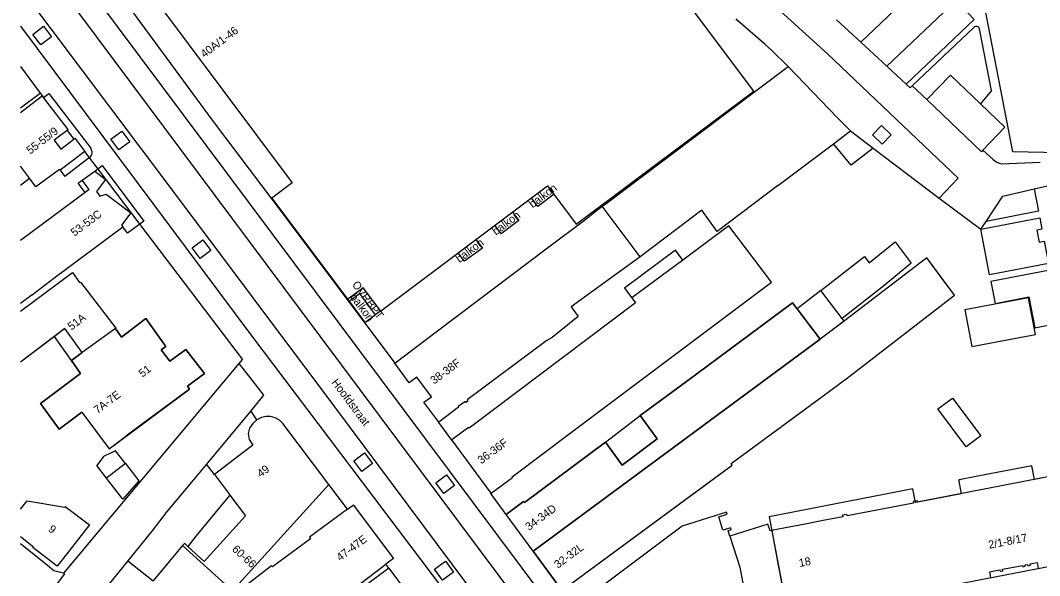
# Model space of a CAD drawing. Extents: x 194485 to 197793, y 468269 to 470822.
# Drawn here: x 194485.4 to 194638.3, y 469431.3 to 469514.5 of the extents above; entities that cross this region are included whole.
import ezdxf

# ---------------------------------------------------------------- set-up
doc = ezdxf.new("R2010")
doc.units = 0
for name, color, linetype in [('BAG plantopografie panden grensvlak pand', 7, 'Continuous'), ('BAG plantopografie panden lijnelement overig', 7, 'Continuous'), ('BAG plantopografie panden tekst opmerking', 7, 'Continuous'), ('BGT begrenzing pand op maaiveld onder overbouw', 7, 'Continuous'), ('BGT grensvlak gebouwinstallatie plus 1', 7, 'Continuous'), ('BGT grensvlak overig bouwwerk', 7, 'Continuous'), ('BGT grensvlak pand deel overbouw', 7, 'Continuous'), ('BGT grensvlak pand min 1', 7, 'Continuous'), ('BGT grensvlak pand op maaiveld', 7, 'Continuous'), ('BGT grensvlak pand op maaiveld LR', 7, 'Continuous'), ('BGT grensvlak wegdeel', 7, 'Continuous'), ('BGT tekst huisnummerreeks', 7, 'Continuous'), ('BGT tekst huisnummerreeks min 1', 7, 'Continuous'), ('BGT tekst openbare ruimte label weg', 7, 'Continuous'), ('GEM grensvlak beperking object', 7, 'Continuous')]:
    doc.layers.add(name, color=color, linetype=linetype)

msp = doc.modelspace()

# ---------------------------------------------------------------- linework, layer by layer
at = {"layer": 'BAG plantopografie panden grensvlak pand'}
for p, q in [((194595.38, 469503.93), (194561.96, 469548.58)), ((194498.06, 469527.77), (194526.18, 469490.2)), ((194568.78, 469484.02), (194595.38, 469503.93)), ((194526.18, 469490.2), (194523.12, 469487.91)), ((194539.4, 469470.98), (194564.48, 469489.76)), ((194564.48, 469489.76), (194568.78, 469484.02)), ((194523.12, 469487.91), (194534.48, 469472.74)), ((194534.7, 469472.44), (194536.26, 469473.6)), ((194536.26, 469473.6), (194538.64, 469470.42)), ((194534.48, 469472.74), (194534.7, 469472.44)), ((194539.4, 469470.98), (194538.64, 469470.42))]:
    msp.add_line(p, q, dxfattribs=at)
at = {"layer": 'BAG plantopografie panden lijnelement overig'}
for p, q in [((194563, 469486.65), (194562.04, 469487.93)), ((194565.44, 469488.48), (194563, 469486.65)), ((194559.21, 469485.82), (194560.17, 469484.53)), ((194560.17, 469484.53), (194557.51, 469482.54)), ((194557.51, 469482.54), (194556.55, 469483.83)), ((194553.73, 469481.71), (194554.69, 469480.43)), ((194552.03, 469478.44), (194551.07, 469479.72)), ((194554.69, 469480.43), (194552.03, 469478.44)), ((194534.48, 469472.74), (194536.79, 469474.47)), ((194536.79, 469474.47), (194539.4, 469470.98)), ((194534.7, 469472.44), (194537.09, 469469.26)), ((194537.09, 469469.26), (194538.64, 469470.42))]:
    msp.add_line(p, q, dxfattribs=at)
at = {"layer": 'BGT begrenzing pand op maaiveld onder overbouw'}
for p, q in [((194492.41, 469498.06), (194490.47, 469496.57)), ((194490.47, 469496.57), (194491.47, 469495.26)), ((194491.47, 469495.26), (194493.41, 469496.75))]:
    msp.add_line(p, q, dxfattribs=at)
for points in [[(194591.81, 469437.24), (194593.3, 469432.6), (194594.45, 469426.43), (194594.35, 469426.4), (194594.73, 469424.46), (194593.08, 469423.93)], [(194598.08, 469438.08), (194599.06, 469432.91), (194600.38, 469426.02)]]:
    msp.add_lwpolyline(points, dxfattribs=at)
at = {"layer": 'BGT grensvlak gebouwinstallatie plus 1'}
for p, q in [((194488.9, 469502.98), (194489.69, 469503.59)), ((194489.69, 469503.59), (194495.98, 469495.37)), ((194609.88, 469497.97), (194613.3, 469495.4)), ((194610.01, 469492.85), (194607.33, 469496.06)), ((194613.3, 469495.4), (194610.01, 469492.85)), ((194495.79, 469493.97), (194492.1, 469491.15)), ((194491.36, 469492.11), (194492.1, 469491.15)), ((194496.56, 469491.97), (194497.69, 469492.81)), ((194497.69, 469492.81), (194503.9, 469484.44)), ((194485.41, 469489.87), (194486.76, 469490.9)), ((194494.09, 469490.13), (194494.7, 469490.59)), ((194495.11, 469488.76), (194494.09, 469490.13)), ((194503.9, 469484.44), (194501.49, 469482.65)), ((194501.49, 469482.65), (194500.79, 469483.59)), ((194605.45, 469474.05), (194601.88, 469471.33)), ((194608.96, 469469.44), (194608.66, 469469.84)), ((194493.1, 469463.57), (194490.52, 469467.17)), ((194573.14, 469451.31), (194578.36, 469455.31))]:
    msp.add_line(p, q, dxfattribs=at)
for points in [[(194584.78, 469478.63), (194583.68, 469480.11), (194576.03, 469474.43), (194577.13, 469472.95)], [(194501.16, 469448.13), (194503.18, 469445.53), (194500.8, 469442.8), (194498.35, 469445.95)], [(194516.83, 469443.4), (194515.54, 469441.85), (194511.71, 469437.26), (194510.5, 469435.7)]]:
    msp.add_lwpolyline(points, dxfattribs=at)
msp.add_arc((194495.18, 469494.76), 1, 307.3973, 37.4081, dxfattribs=at)
at = {"layer": 'BGT grensvlak overig bouwwerk'}
msp.add_lwpolyline([(194613.2, 469497.39), (194614.53, 469498.77), (194615.98, 469497.37), (194614.65, 469496), (194613.2, 469497.39)], dxfattribs=at)
at = {"layer": 'BGT grensvlak pand deel overbouw'}
msp.add_line((194492.41, 469498.06), (194493.41, 469496.75), dxfattribs=at)
msp.add_lwpolyline([(194598.08, 469438.08), (194597.84, 469438.04), (194597.52, 469439.04), (194594.67, 469438.14), (194591.81, 469437.24)], dxfattribs=at)
at = {"layer": 'BGT grensvlak pand min 1'}
msp.add_lwpolyline([(194600.54, 469425.14), (194657.87, 469436.23), (194657.64, 469437.39), (194662.3, 469444.43), (194663.53, 469444.64), (194664.1, 469445.45), (194663.92, 469446.41), (194663.11, 469446.92), (194662.42, 469450.59), (194619.66, 469442.27), (194619.26, 469444.32), (194597.68, 469440.12), (194600.54, 469425.14)], dxfattribs=at)
at = {"layer": 'BGT grensvlak pand op maaiveld'}
for p, q in [((194485.41, 469507.61), (194488.38, 469503.66)), ((194573.45, 469487.26), (194600.53, 469507.63)), ((194485.41, 469501.43), (194488.38, 469503.66)), ((194488.71, 469503.22), (194485.41, 469500.69)), ((194488.9, 469502.98), (194488.71, 469503.22)), ((194607.33, 469496.06), (194609.88, 469497.97)), ((194598.95, 469489.76), (194607.33, 469496.06)), ((194495.08, 469494.9), (194491.36, 469492.11)), ((194486.76, 469490.9), (194485.41, 469492.71)), ((194494.7, 469490.59), (194496.56, 469491.97)), ((194496.56, 469491.97), (194498.14, 469490.77)), ((194495.72, 469489.21), (194494.7, 469490.59)), ((194498.2, 469490.7), (194496.83, 469488.89)), ((194498.14, 469490.77), (194498.21, 469490.72)), ((194498.21, 469490.72), (194498.2, 469490.7)), ((194495.72, 469489.21), (194495.11, 469488.76)), ((194496.83, 469488.89), (194497.35, 469488.18)), ((194495.11, 469488.76), (194485.41, 469481.56)), ((194497.35, 469488.18), (194498.27, 469488.52)), ((194498.27, 469488.52), (194501.99, 469485.7)), ((194571.57, 469485.83), (194572.68, 469486.68)), ((194572.68, 469486.68), (194573.45, 469487.26)), ((194587.6, 469486.1), (194578.36, 469479.13)), ((194629.44, 469483.23), (194629.44, 469483.24)), ((194616.6, 469481.33), (194619.01, 469478.16)), ((194547.96, 469468.02), (194564.46, 469480.45)), ((194578.36, 469479.13), (194568, 469471.59)), ((194584.78, 469478.63), (194577.13, 469472.95)), ((194624.16, 469475.16), (194621.33, 469478.96)), ((194608.66, 469469.84), (194605.45, 469474.05)), ((194487.16, 469473.43), (194485.41, 469472.09)), ((194605.35, 469466.78), (194601.88, 469471.33)), ((194608.96, 469469.44), (194605.35, 469466.78)), ((194499.72, 469468.4), (194499.66, 469468.36)), ((194541.55, 469463.19), (194547.96, 469468.02)), ((194490.52, 469467.17), (194485.41, 469463.34)), ((194493.1, 469463.57), (194494.68, 469464.79)), ((194555.99, 469443.67), (194550.12, 469451.67)), ((194501.16, 469448.13), (194499.7, 469450.03)), ((194498.35, 469445.95), (194496.88, 469447.85)), ((194501.16, 469448.13), (194498.35, 469445.95))]:
    msp.add_line(p, q, dxfattribs=at)
for points in [[(194641.2, 469494.68), (194634.23, 469494.84), (194629.28, 469520.44)], [(194600.53, 469507.63), (194607.92, 469500), (194609.88, 469497.97)], [(194492.41, 469498.06), (194492.57, 469498.18), (194488.9, 469502.98)], [(194493.41, 469496.75), (194493.57, 469496.87), (194495.08, 469494.9)], [(194491.36, 469492.11), (194491.28, 469492.21), (194487.73, 469489.6), (194486.76, 469490.9)], [(194598.95, 469489.76), (194589.92, 469482.92), (194587.6, 469486.1)], [(194637.43, 469489.32), (194638.09, 469485.93), (194630.23, 469484.41)], [(194630.23, 469484.41), (194632.76, 469488.18), (194637.43, 469489.32)], [(194564.46, 469480.45), (194570.19, 469484.77), (194571.57, 469485.83)], [(194501.99, 469485.7), (194500.59, 469483.85), (194500.79, 469483.59)], [(194629.44, 469483.24), (194638.28, 469484.96), (194638.61, 469483.24), (194637.85, 469483.1), (194638.21, 469481.29), (194638.96, 469481.43), (194639.61, 469478.11), (194630.76, 469476.4), (194629.44, 469483.23)], [(194487.16, 469473.43), (194490.45, 469475.9), (194500.79, 469483.59)], [(194555.99, 469443.67), (194559.22, 469446.04), (194559.16, 469446.14), (194568.64, 469453.28), (194585.45, 469465.86), (194598.04, 469475.33), (194591.66, 469483.74), (194584.78, 469478.63)], [(194605.45, 469474.05), (194611.99, 469479.14), (194612.69, 469478.23), (194616.6, 469481.33)], [(194619.01, 469478.16), (194614.9, 469474.76), (194608.66, 469469.84)], [(194621.33, 469478.96), (194609.02, 469469.49), (194608.96, 469469.44)], [(194485.41, 469470.97), (194493.25, 469476.75), (194494.3, 469475.26), (194494.41, 469475.31), (194499.72, 469468.4)], [(194630.95, 469475.41), (194631.59, 469472.12), (194636.64, 469473.11), (194637.56, 469468.44), (194641.33, 469469.19), (194639.8, 469477.13), (194630.95, 469475.41)], [(194566.73, 469429.01), (194567.24, 469429.38), (194567.15, 469429.52), (194586.9, 469444.03), (194592.14, 469447.88), (194592.02, 469448.12), (194605.61, 469458.1), (194609.65, 469461.12), (194625.5, 469473.36), (194624.16, 469475.16)], [(194577.13, 469472.95), (194577.68, 469472.2), (194552.71, 469453.41), (194552.61, 469453.53), (194550.12, 469451.67)], [(194601.88, 469471.33), (194601.2, 469472.22), (194585.33, 469460.44), (194578.36, 469455.31)], [(194627.05, 469471.18), (194628.09, 469465.66), (194634.44, 469466.85), (194637.62, 469467.45), (194636.58, 469472.98), (194627.05, 469471.18)], [(194568, 469471.59), (194569.06, 469470.14), (194565.14, 469467), (194564.38, 469466.55), (194552.39, 469457.65), (194552.49, 469457.47), (194552.27, 469457.29), (194552.16, 469457.42), (194551.05, 469456.67), (194551.12, 469456.55), (194548.16, 469454.32)], [(194499.66, 469468.36), (194500.56, 469467.05), (194504.21, 469469.84), (194507.23, 469465.68), (194506.52, 469465.18), (194507.8, 469463.49), (194510.24, 469465.24), (194513.03, 469461.6), (194510.46, 469459.71), (194510.79, 469459.27), (194501.44, 469452.36)], [(194494.68, 469464.79), (194492.09, 469468.34), (194490.52, 469467.17)], [(194494.61, 469455.83), (194491.24, 469453.3), (194488.44, 469457.12), (194494.45, 469461.61), (194493.1, 469463.57)], [(194548.16, 469454.32), (194545.93, 469457.31), (194547.07, 469458.13), (194544.88, 469461.09), (194543.72, 469460.2), (194541.55, 469463.19)], [(194623.02, 469456.33), (194625.2, 469457.94), (194629.44, 469452.26), (194627.23, 469450.64), (194623.02, 469456.33)], [(194494.61, 469455.83), (194498.71, 469450.34), (194501.44, 469452.36)], [(194531.68, 469444.96), (194524.79, 469454.13), (194524.26, 469454.61), (194523.63, 469454.98), (194522.94, 469455.18), (194522.25, 469455.19), (194521.56, 469455.03), (194520.89, 469454.7)], [(194578.36, 469455.31), (194580.9, 469451.82), (194575.64, 469447.9), (194573.14, 469451.31)], [(194520.89, 469454.7), (194520.25, 469454.14), (194519.78, 469453.42), (194519.59, 469452.62), (194519.72, 469451.71), (194520.29, 469450.86), (194518.84, 469449.77), (194514.51, 469446.49)], [(194573.14, 469451.31), (194560.99, 469442.3), (194560.88, 469442.44), (194558.26, 469440.5)], [(194499.7, 469450.03), (194497.86, 469449.18), (194496.88, 469447.85)], [(194644.03, 469447.01), (194637.5, 469445.75), (194637.11, 469447.79), (194630.54, 469446.51), (194626.43, 469445.71), (194626.3, 469445.69), (194626.18, 469445.66), (194626.12, 469445.65), (194626.15, 469445.46), (194626.52, 469443.6), (194619.99, 469442.33), (194619.94, 469442.56), (194619.69, 469442.51), (194619.37, 469442.45), (194619.29, 469442.43), (194619.33, 469442.2), (194609.39, 469440.27), (194609.34, 469440.5), (194608.69, 469440.37), (194608.73, 469440.15), (194605.82, 469439.58), (194603.09, 469439.05), (194598.3, 469438.12), (194598.2, 469438.1), (194598.08, 469438.08)], [(194514.51, 469446.49), (194516.79, 469443.46), (194516.83, 469443.4)], [(194509.71, 469435.86), (194517.2, 469429.05), (194531.68, 469444.96)], [(194516.83, 469443.4), (194519.18, 469440.28), (194512.95, 469433.46), (194510.5, 469435.7)], [(194485.41, 469441.27), (194486.42, 469442.55), (194492.09, 469441.59), (194492.12, 469441.69), (194495.77, 469438.93), (194490.93, 469432.75)], [(194534.46, 469441.27), (194535.3, 469441.9), (194535.34, 469441.92), (194541.35, 469433.89), (194540.24, 469433.05)], [(194534.46, 469441.27), (194528.79, 469437.08), (194528.92, 469436.84), (194523.21, 469432.64), (194523.07, 469432.81), (194506.8, 469420.26)], [(194562.31, 469434.97), (194558.25, 469440.49), (194558.26, 469440.5)], [(194591.81, 469437.24), (194591.55, 469438.06), (194592.02, 469438.22), (194591.94, 469438.5), (194590.77, 469438.13), (194590.14, 469440.14), (194591.41, 469440.54), (194591.31, 469440.84), (194584.68, 469438.73), (194572.88, 469429.9), (194570.53, 469428.14)], [(194490.93, 469432.75), (194487.29, 469435.52), (194487.38, 469435.6), (194485.41, 469437.15)], [(194510.5, 469435.7), (194510.1, 469436.08), (194510.01, 469436.16), (194509.71, 469435.86)], [(194566.73, 469429.01), (194566.73, 469429.01), (194562.31, 469434.97)], [(194512.54, 469412.81), (194512.72, 469412.58), (194528.69, 469424.55), (194528.62, 469424.76), (194534.77, 469429.2), (194534.92, 469429), (194540.24, 469433.05)], [(194540.69, 469432.46), (194528.13, 469423.12), (194530.88, 469419.32), (194531.5, 469419.73), (194540.88, 469406.92), (194540.29, 469406.55), (194543.77, 469401.87), (194545.64, 469403.29)], [(194540.69, 469432.46), (194553.07, 469415.78), (194553.11, 469415.72)], [(194630.51, 469430.93), (194630.97, 469431.02), (194630.8, 469431.91), (194631.51, 469432.04), (194632.32, 469432.2), (194632.36, 469431.99), (194632.75, 469432.06), (194632.71, 469432.28), (194635.69, 469432.86), (194635.73, 469432.64), (194636.11, 469432.72), (194636.07, 469432.93), (194636.46, 469433.01), (194636.51, 469432.79), (194636.89, 469432.87), (194636.85, 469433.09), (194637.33, 469433.18), (194637.88, 469433.29), (194638.05, 469432.39), (194638.55, 469432.49)]]:
    msp.add_lwpolyline(points, dxfattribs=at)
at = {"layer": 'BGT grensvlak pand op maaiveld LR'}
for p, q in [((194578.36, 469479.13), (194572.68, 469486.68)), ((194499.66, 469468.36), (194494.68, 469464.79)), ((194562.31, 469434.97), (194605.35, 469466.78))]:
    msp.add_line(p, q, dxfattribs=at)
at = {"layer": 'BGT grensvlak wegdeel'}
for p, q in [((194489.33, 469527.8), (194546.18, 469451.79)), ((194625.74, 469517.54), (194615.34, 469507.67)), ((194593.02, 469514.49), (194592.73, 469514.76)), ((194597.03, 469510.96), (194593.02, 469514.49)), ((194628.4, 469513.5), (194619.17, 469504.73)), ((194631.05, 469504.02), (194629.26, 469513.28)), ((194615.34, 469507.67), (194611.43, 469511.3)), ((194618.24, 469504.98), (194615.34, 469507.67)), ((194618.84, 469504.42), (194618.24, 469504.98)), ((194619.17, 469504.73), (194618.84, 469504.42)), ((194619.17, 469504.73), (194621.37, 469502.69)), ((194488.38, 469503.66), (194488.71, 469503.22)), ((194629.55, 469494.86), (194621.37, 469502.69)), ((194631.05, 469504.02), (194629.38, 469502.05)), ((194613.3, 469495.4), (194623.21, 469487.92)), ((194629.77, 469495.09), (194629.55, 469494.86)), ((194629.77, 469495.09), (194631.24, 469493.73)), ((194503.38, 469483.96), (194495.08, 469494.9)), ((194632.52, 469493.03), (194638.34, 469493.31)), ((194637.43, 469489.32), (194640.36, 469489.95)), ((194623.21, 469487.92), (194629.44, 469483.23)), ((194629.44, 469483.24), (194630.23, 469484.41)), ((194518.74, 469463.79), (194503.38, 469483.96)), ((194518.19, 469463.14), (194491.89, 469431.69)), ((194518.74, 469463.79), (194518.19, 469463.14)), ((194519.96, 469456.04), (194513.34, 469448.05)), ((194520.89, 469454.7), (194519.96, 469456.04)), ((194546.18, 469451.79), (194566.24, 469424.96)), ((194514.51, 469446.49), (194513.34, 469448.05)), ((194534.46, 469441.27), (194531.68, 469444.96)), ((194489.46, 469432.83), (194485.41, 469436.1)), ((194509.71, 469435.86), (194505.3, 469430.53)), ((194501.54, 469433.56), (194497.89, 469429.03)), ((194501.54, 469433.56), (194505.3, 469430.53)), ((194540.69, 469432.46), (194540.24, 469433.05)), ((194492.05, 469431.57), (194488.91, 469427.55)), ((194492.05, 469431.57), (194491.89, 469431.69))]:
    msp.add_line(p, q, dxfattribs=at)
for points in [[(194491.72, 469529.6), (194495.66, 469524.77), (194514.32, 469499.38), (194525.12, 469485.09), (194541.55, 469463.19)], [(194611.43, 469511.3), (194623.56, 469522.81), (194626.7, 469525.17), (194624.2, 469528.3)], [(194486.62, 469525.78), (194527.36, 469471.14), (194560.25, 469427.17)], [(194623.21, 469487.92), (194626.04, 469490.88), (194606.45, 469509.54), (194591.27, 469523.36)], [(194485.41, 469519.38), (194508.02, 469489.28), (194532.51, 469456.6), (194552.3, 469430.08)], [(194618.24, 469504.98), (194628.45, 469514.68), (194625.74, 469517.54)], [(194485.41, 469513.67), (194520.14, 469467.24), (194536.67, 469445.35), (194554.25, 469422.05)], [(194488.87, 469513.67), (194490.08, 469512.08), (194488.5, 469510.86), (194487.28, 469512.45), (194488.87, 469513.67)], [(194611.43, 469511.3), (194609.59, 469513), (194607.79, 469514.64)], [(194597.03, 469510.96), (194598.1, 469510.01), (194600.53, 469507.63)], [(194621.37, 469502.69), (194624.88, 469506.35), (194629.38, 469502.05)], [(194629.38, 469502.05), (194633.06, 469498.53), (194629.77, 469495.09)], [(194500.61, 469497.96), (194501.8, 469496.33), (194500.18, 469495.14), (194498.99, 469496.76), (194500.61, 469497.96)], [(194512.77, 469481.67), (194513.97, 469480.08), (194512.38, 469478.88), (194511.19, 469480.47), (194512.77, 469481.67)], [(194518.19, 469463.14), (194520.17, 469460.56), (194521.88, 469458.36), (194519.96, 469456.04)], [(194550.12, 469451.67), (194550.1, 469451.65), (194548.14, 469454.3), (194548.16, 469454.32)], [(194537.02, 469449.73), (194538.21, 469448.12), (194536.61, 469446.92), (194535.4, 469448.53), (194537.02, 469449.73)], [(194513.34, 469448.05), (194511.31, 469445.61), (194507.44, 469440.97), (194505.12, 469437.99), (194501.54, 469433.56)], [(194548.92, 469443.61), (194547.72, 469445.22), (194549.33, 469446.42), (194550.52, 469444.81), (194548.92, 469443.61)], [(194558.26, 469440.5), (194555.96, 469443.64), (194555.99, 469443.67)], [(194491.89, 469431.69), (194490.41, 469432.05), (194489.46, 469432.83)], [(194549.14, 469433.47), (194550.34, 469431.86), (194548.73, 469430.66), (194547.53, 469432.27), (194549.14, 469433.47)]]:
    msp.add_lwpolyline(points, dxfattribs=at)
for centre, radius, start, end in [((194628.77, 469513.14), 0.513, 15.3449, 135.7708), ((194633.79, 469496.85), 4.03, 230.8123, 251.7037)]:
    msp.add_arc(centre, radius, start, end, dxfattribs=at)
at = {"layer": 'GEM grensvlak beperking object'}
for p, q in [((194499.66, 469468.36), (194494.68, 469464.79)), ((194605.35, 469466.78), (194562.31, 469434.97))]:
    msp.add_line(p, q, dxfattribs=at)
for points in [[(194562.31, 469434.97), (194566.73, 469429.01), (194567.24, 469429.38), (194567.15, 469429.52), (194592.14, 469447.88), (194592.02, 469448.12), (194605.61, 469458.1), (194609.65, 469461.12), (194625.5, 469473.36), (194621.33, 469478.96), (194609.02, 469469.49), (194605.35, 469466.78)], [(194485.41, 469470.97), (194493.25, 469476.75), (194494.3, 469475.26), (194494.41, 469475.31), (194499.72, 469468.4), (194499.66, 469468.36)], [(194562.31, 469434.97), (194558.25, 469440.49), (194560.88, 469442.44), (194560.99, 469442.3), (194573.14, 469451.31), (194575.64, 469447.9), (194580.9, 469451.82), (194578.36, 469455.31), (194585.33, 469460.44), (194601.2, 469472.22), (194605.35, 469466.78)], [(194494.68, 469464.79), (194493.1, 469463.57), (194494.45, 469461.61), (194488.44, 469457.12), (194491.24, 469453.3), (194494.61, 469455.83), (194498.71, 469450.34), (194510.79, 469459.27), (194510.46, 469459.71), (194513.03, 469461.6), (194510.24, 469465.24), (194507.8, 469463.49), (194506.52, 469465.18), (194507.23, 469465.68), (194504.21, 469469.84), (194500.56, 469467.05), (194499.66, 469468.36)], [(194494.68, 469464.79), (194492.09, 469468.34), (194485.41, 469463.34)], [(194485.41, 469441.27), (194486.42, 469442.55), (194492.09, 469441.59), (194492.12, 469441.69), (194495.77, 469438.93), (194490.93, 469432.75), (194487.29, 469435.52), (194487.38, 469435.6), (194485.41, 469437.15)]]:
    msp.add_lwpolyline(points, dxfattribs=at)

# ---------------------------------------------------------------- texts
at = {"layer": 'BAG plantopografie panden tekst opmerking'}
for s, rotation, p in [('40A/1-46', 36.8126, (194512.99, 469508.88)), ('balkon', 36.8126, (194562.22, 469486.37)), ('balkon', 36.8126, (194556.73, 469482.27)), ('balkon', 36.8126, (194551.25, 469478.16)), ('OVRBPT', 306.8126, (194535.08, 469474.94)), ('balkon', 306.8126, (194534.77, 469473.07))]:
    msp.add_text(s, height=1.2, rotation=rotation, dxfattribs=at).set_placement(p)
at = {"layer": 'BGT tekst huisnummerreeks'}
for s, rotation, p in [('55-55/9', 37.4, (194486.88, 469494.42)), ('53-53C', 36.8, (194493.52, 469482.11)), ('51A', 37.6, (194493.08, 469468.03)), ('38-38F', 36.5, (194547.45, 469459.95)), ('51', 37.1, (194503.71, 469460.98)), ('7A-7E', 36.8, (194496.98, 469455.52)), ('36-36F', 36.3, (194554.53, 469448)), ('49', 36.9, (194521.45, 469445.98)), ('34-34D', 36.3, (194561.68, 469438.02)), ('9', 322, (194489.49, 469438.09)), ('47-47E', 36.8, (194533.37, 469433.44)), ('2/1-8/17', 11, (194630.71, 469435.35)), ('60-66', 317.6, (194517.06, 469435.15)), ('32-32L', 36.5, (194566.01, 469432.35))]:
    msp.add_text(s, height=1.2, rotation=rotation, dxfattribs=at).set_placement(p)
at = {"layer": 'BGT tekst huisnummerreeks min 1'}
msp.add_text('18', height=1.2, rotation=10.8, dxfattribs=at).set_placement((194602.28, 469432.62))
at = {"layer": 'BGT tekst openbare ruimte label weg'}
msp.add_text('Hoofdstraat', height=1.2, rotation=307, dxfattribs=at).set_placement((194531.99, 469460.26))

doc.saveas('drawing.dxf')
